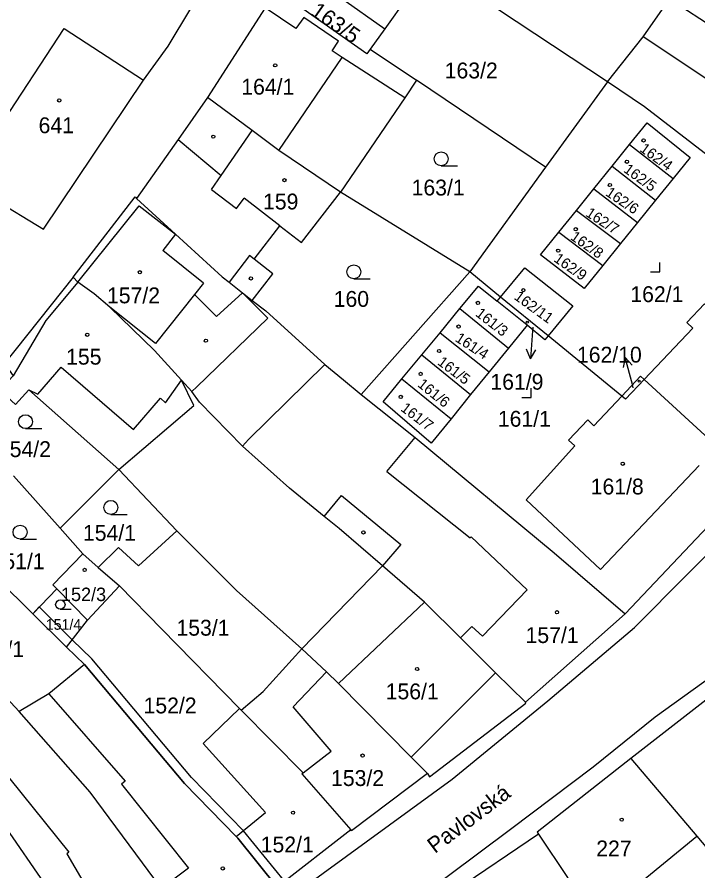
# Model space of a CAD drawing. Extents: x -600849 to -599899, y -1204328 to -1203436.
# Drawn here: x -600525.3 to -600452.2, y -1203727 to -1203635.4 of the extents above; entities that cross this region are included whole.
import ezdxf

# ---------------------------------------------------------------- set-up
doc = ezdxf.new("R2010")
doc.units = 0
for name, color, linetype in [('Vrstva 1', 7, 'Continuous'), ('Vrstva 13', 7, 'Continuous'), ('Vrstva 2', 7, 'Continuous'), ('Vrstva 3', 7, 'Continuous'), ('Vrstva 4', 7, 'Continuous'), ('Vrstva 5', 7, 'Continuous'), ('Vrstva 7', 7, 'Continuous')]:
    doc.layers.add(name, color=color, linetype=linetype)

msp = doc.modelspace()

# ---------------------------------------------------------------- linework, layer by layer
at = {"layer": 'Vrstva 1'}
for p, q in [((-600480.89, -1203629.76), (-600485.82, -1203636.68)), ((-600493.96, -1203630.88), (-600485.82, -1203636.68)), ((-600461.92, -1203642.39), (-600477.46, -1203632.09)), ((-600443.46, -1203641.26), (-600455.29, -1203633.46)), ((-600498.63, -1203634.44), (-600504.83, -1203644.05)), ((-600485.82, -1203636.68), (-600487.37, -1203638.87)), ((-600487.37, -1203638.87), (-600482.41, -1203642.21)), ((-600468.57, -1203651.53), (-600482.41, -1203642.21)), ((-600461.92, -1203642.39), (-600468.57, -1203651.53)), ((-600457.96, -1203645.05), (-600461.92, -1203642.39)), ((-600461.42, -1203651.42), (-600459.56, -1203649.11)), ((-600459.56, -1203649.11), (-600454.89, -1203652.74)), ((-600468.57, -1203651.53), (-600476.69, -1203662.78)), ((-600463.38, -1203653.85), (-600461.42, -1203651.42)), ((-600461.42, -1203651.42), (-600456.77, -1203655.07)), ((-600454.89, -1203652.74), (-600456.77, -1203655.07)), ((-600476.69, -1203662.78), (-600490.56, -1203654.23)), ((-600465.25, -1203656.17), (-600463.38, -1203653.85)), ((-600463.38, -1203653.85), (-600458.71, -1203657.46)), ((-600456.77, -1203655.07), (-600458.71, -1203657.46)), ((-600467.13, -1203658.49), (-600465.25, -1203656.17)), ((-600465.25, -1203656.17), (-600460.53, -1203659.71)), ((-600458.71, -1203657.46), (-600460.53, -1203659.71)), ((-600467.13, -1203658.49), (-600462.44, -1203662.08)), ((-600460.53, -1203659.71), (-600462.44, -1203662.08)), ((-600519.23, -1203663.35), (-600526.62, -1203672.61)), ((-600488.35, -1203675.92), (-600476.69, -1203662.78)), ((-600473.4, -1203665.48), (-600476.69, -1203662.78)), ((-600473.77, -1203665.92), (-600473.4, -1203665.48)), ((-600468.3, -1203669.64), (-600473.4, -1203665.48)), ((-600470.56, -1203668.5), (-600473.77, -1203665.92)), ((-600479.88, -1203669.3), (-600477.76, -1203666.71)), ((-600477.76, -1203666.71), (-600472.55, -1203670.96)), ((-600470.56, -1203668.5), (-600472.55, -1203670.96)), ((-600481.84, -1203671.68), (-600479.88, -1203669.3)), ((-600479.88, -1203669.3), (-600474.62, -1203673.49)), ((-600460.4, -1203676.09), (-600468.3, -1203669.64)), ((-600472.55, -1203670.96), (-600474.62, -1203673.49)), ((-600483.97, -1203674.26), (-600481.84, -1203671.68)), ((-600481.84, -1203671.68), (-600476.61, -1203675.93)), ((-600474.62, -1203673.49), (-600476.61, -1203675.93)), ((-600483.97, -1203674.26), (-600478.71, -1203678.52)), ((-600450.16, -1203681.49), (-600457.99, -1203674.31)), ((-600476.61, -1203675.93), (-600478.71, -1203678.52)), ((-600520.64, -1203690.25), (-600525.62, -1203684.64)), ((-600514.34, -1203683.98), (-600520.64, -1203690.25)), ((-600508.13, -1203690.57), (-600514.34, -1203683.98)), ((-600520.64, -1203690.25), (-600518.19, -1203693.01)), ((-600518.19, -1203693.01), (-600516.56, -1203694.48)), ((-600516.56, -1203694.48), (-600514.28, -1203696.45)), ((-600528.21, -1203694.86), (-600523.58, -1203699.44)), ((-600514.28, -1203696.45), (-600517.7, -1203700.15)), ((-600523.58, -1203699.44), (-600520.99, -1203696.78)), ((-600517.7, -1203700.15), (-600520.99, -1203696.78)), ((-600519.95, -1203703.04), (-600523.58, -1203699.44)), ((-600519.95, -1203703.04), (-600517.7, -1203700.15)), ((-600460.04, -1203699.45), (-600470.74, -1203708.95)), ((-600518.02, -1203704.91), (-600519.95, -1203703.04)), ((-600518.02, -1203704.91), (-600521.86, -1203708.03)), ((-600448.26, -1203706.28), (-600459.42, -1203714.97)), ((-600525.04, -1203709.94), (-600527.47, -1203707.35)), ((-600521.86, -1203708.03), (-600525.04, -1203709.94)), ((-600505.3, -1203713.38), (-600501.38, -1203709.63)), ((-600501.38, -1203709.63), (-600501.21, -1203709.81)), ((-600489.46, -1203722.64), (-600497.34, -1203728.8)), ((-600469.34, -1203723.1), (-600480.16, -1203730.41))]:
    msp.add_line(p, q, dxfattribs=at)
for points in [[(-600468.32, -1203708.8), (-600459.02, -1203700.91), (-600447.7, -1203689.53), (-600398.8, -1203640.57), (-600381.76, -1203623.36), (-600376.64, -1203618.38), (-600366.85, -1203610.56), (-600358.79, -1203604.64), (-600335.27, -1203586.75), (-600326.92, -1203580.15), (-600315.47, -1203571.41), (-600313.87, -1203569.96), (-600309.19, -1203565.44), (-600307.64, -1203563.87), (-600297.75, -1203553.71), (-600294.09, -1203550.64), (-600277.89, -1203537.3), (-600263.22, -1203524.94), (-600248.8, -1203512.9), (-600231.21, -1203497.85)], [(-600516.74, -1203754.05), (-600500.93, -1203742.85), (-600482.23, -1203729.97), (-600472.33, -1203722.55), (-600463.46, -1203715.87), (-600456.83, -1203710.5), (-600450.71, -1203706.1), (-600424.21, -1203680.79), (-600406.92, -1203664.19), (-600381.77, -1203639.93), (-600378.09, -1203636.25), (-600365.25, -1203624.15), (-600362.86, -1203622.3), (-600356.33, -1203617.3), (-600346.34, -1203609.78), (-600334.21, -1203600.46), (-600309.35, -1203581.63), (-600259.57, -1203537.67), (-600253.46, -1203531.77)], [(-600487.37, -1203638.87), (-600487.73, -1203639.37), (-600495.91, -1203633.62), (-600495.64, -1203633.24)], [(-600461.92, -1203642.39), (-600458.12, -1203637.56), (-600455.29, -1203633.46)], [(-600527.86, -1203654.9), (-600522.41, -1203658.19), (-600511.68, -1203642.2), (-600509.04, -1203638.54), (-600506.63, -1203634.51)], [(-600482.41, -1203642.21), (-600483.66, -1203644.11), (-600490.56, -1203654.23)], [(-600504.83, -1203644.05), (-600507.99, -1203648.55), (-600512.45, -1203654.88)], [(-600490.56, -1203654.23), (-600497.17, -1203649.74), (-600500.04, -1203647.61), (-600504.83, -1203644.05)], [(-600430.59, -1203668.48), (-600435.56, -1203663.69), (-600446.11, -1203655.07), (-600451.09, -1203650.36), (-600457.96, -1203645.05)], [(-600459.56, -1203649.11), (-600457.67, -1203646.77), (-600453.07, -1203650.49), (-600454.89, -1203652.74)], [(-600500.03, -1203665.83), (-600497.83, -1203662.99), (-600499.84, -1203661.41), (-600497.07, -1203657.82), (-600494.76, -1203659.61), (-600490.56, -1203654.23)], [(-600519.23, -1203663.35), (-600512.6, -1203654.73), (-600512.45, -1203654.88)], [(-600512.45, -1203654.88), (-600508.26, -1203658.71), (-600503.26, -1203663.3), (-600502.52, -1203663.88), (-600501.09, -1203665), (-600500.03, -1203665.83)], [(-600462.44, -1203662.08), (-600464.44, -1203664.56), (-600469.1, -1203660.94), (-600467.13, -1203658.49)], [(-600457.99, -1203674.31), (-600452.79, -1203668.81), (-600453.42, -1203668.19), (-600451.54, -1203666.19), (-600450.87, -1203666.76), (-600445.65, -1203661.21), (-600437.84, -1203668.56), (-600440.62, -1203671.46), (-600439.79, -1203672.28), (-600446.52, -1203679.36), (-600447.21, -1203678.64), (-600450.16, -1203681.49)], [(-600473.4, -1203665.48), (-600470.79, -1203662.32), (-600465.65, -1203666.41), (-600468.3, -1203669.64)], [(-600507.63, -1203674.37), (-600510.52, -1203671.2), (-600515.31, -1203666.56), (-600517, -1203665.14), (-600518.72, -1203663.86), (-600519.23, -1203663.35)], [(-600477.76, -1203666.71), (-600475.77, -1203664.31), (-600473.77, -1203665.92)], [(-600500.03, -1203665.83), (-600498.57, -1203666.95), (-600492.25, -1203672.71)], [(-600468.3, -1203669.64), (-600468.64, -1203670.05), (-600470.56, -1203668.5)], [(-600526.62, -1203672.61), (-600525.67, -1203673.91), (-600527.13, -1203675.45), (-600525.43, -1203677), (-600523.99, -1203675.43), (-600514.34, -1203683.98)], [(-600492.25, -1203672.71), (-600500.42, -1203680.77), (-600501.09, -1203681.48)], [(-600492.25, -1203672.71), (-600490.26, -1203674.36), (-600488.35, -1203675.92)], [(-600514.34, -1203683.98), (-600506.29, -1203677.1), (-600507.63, -1203674.37)], [(-600501.09, -1203681.48), (-600505.7, -1203676.76), (-600506.51, -1203675.6), (-600507.63, -1203674.37)], [(-600478.71, -1203678.52), (-600480.84, -1203681.14), (-600485.98, -1203676.7), (-600483.97, -1203674.26)], [(-600460.4, -1203676.09), (-600458.39, -1203673.95), (-600457.99, -1203674.31)], [(-600457.99, -1203674.31), (-600459.99, -1203676.43), (-600460.4, -1203676.09)], [(-600488.35, -1203675.92), (-600482.56, -1203680.54), (-600467.64, -1203692.93), (-600460.04, -1203699.45)], [(-600452.11, -1203683.55), (-600462.69, -1203694.7), (-600470.65, -1203687.23), (-600465.44, -1203681.45), (-600466.1, -1203680.84), (-600464.04, -1203678.65), (-600463.39, -1203679.27), (-600460.4, -1203676.09)], [(-600470.74, -1203708.95), (-600473.94, -1203705.78), (-600477.71, -1203702.03), (-600481.56, -1203698.21), (-600486.07, -1203694.32), (-600490.72, -1203690.31), (-600492.32, -1203689.01), (-600496.04, -1203685.99), (-600501.09, -1203681.48)], [(-600460.04, -1203699.45), (-600448.61, -1203687.36), (-600448.84, -1203687.11)], [(-600516.56, -1203694.48), (-600514.36, -1203692.35), (-600512.23, -1203694.31), (-600508.13, -1203690.57)], [(-600508.13, -1203690.57), (-600501.72, -1203696.94), (-600494.71, -1203703.2)], [(-600520.99, -1203696.78), (-600521.41, -1203696.35), (-600518.19, -1203693.01)], [(-600514.28, -1203696.45), (-600509.73, -1203701.1), (-600501.38, -1203709.63)], [(-600501.21, -1203709.81), (-600498.86, -1203707.78), (-600494.71, -1203703.2)], [(-600494.71, -1203703.2), (-600492.05, -1203705.68), (-600490.79, -1203706.92), (-600482.98, -1203714.84), (-600481.24, -1203716.6)], [(-600501.74, -1203723.36), (-600507.31, -1203717.65), (-600518.02, -1203704.91)], [(-600514.56, -1203740.22), (-600518.55, -1203733.82), (-600530.21, -1203716.96), (-600533.65, -1203713.17), (-600537.95, -1203708.73)], [(-600503.75, -1203735.54), (-600478.6, -1203717.19), (-600468.32, -1203708.8)], [(-600481.24, -1203716.6), (-600481.03, -1203716.94), (-600470.68, -1203709.05), (-600470.74, -1203708.95)], [(-600505.91, -1203735.13), (-600509.78, -1203728.93), (-600517.42, -1203718.58), (-600525.04, -1203709.94)], [(-600501.21, -1203709.81), (-600494.58, -1203716.51), (-600494.72, -1203716.63), (-600489.46, -1203722.64)], [(-600501.74, -1203723.36), (-600498.61, -1203720.79), (-600505.3, -1203713.38)], [(-600459.42, -1203714.97), (-600469.47, -1203722.88), (-600469.34, -1203723.1)], [(-600459.42, -1203714.97), (-600452.35, -1203723.33), (-600449.14, -1203727.13), (-600448.79, -1203726.83), (-600431.48, -1203744.63), (-600426.82, -1203748.42), (-600419.28, -1203756.23), (-600409.09, -1203765.55), (-600409.58, -1203766.13)], [(-600481.24, -1203716.6), (-600489.4, -1203722.74), (-600489.46, -1203722.64)], [(-600469.34, -1203723.1), (-600466.22, -1203727.76), (-600462.39, -1203731.53), (-600461.96, -1203731.92), (-600457.59, -1203735.9), (-600452.74, -1203740.82), (-600433.78, -1203757.11)], [(-600497.34, -1203728.8), (-600501.57, -1203723.53), (-600501.74, -1203723.36)]]:
    msp.add_lwpolyline(points, dxfattribs=at)
at = {"layer": 'Vrstva 13'}
msp.add_lwpolyline([(-600523.58, -1203699.44), (-600519.95, -1203703.04), (-600518.02, -1203704.91), (-600507.31, -1203717.65), (-600501.74, -1203723.36), (-600501.57, -1203723.53), (-600497.34, -1203728.8), (-600496.55, -1203728.18), (-600500.97, -1203722.73), (-600506.54, -1203717.01), (-600517.25, -1203704.27), (-600519.34, -1203702.25), (-600522.88, -1203698.72)], close=True, dxfattribs=at)
at = {"layer": 'Vrstva 3'}
for p, q in [((-600479.773, -1203651.39), (-600478.023, -1203651.39)), ((-600456.3, -1203662.77), (-600456.3, -1203661.77)), ((-600457.301, -1203662.77), (-600456.3, -1203662.77)), ((-600489.133, -1203663.51), (-600487.383, -1203663.51)), ((-600470.11, -1203676.23), (-600470.11, -1203675.23)), ((-600471.111, -1203676.23), (-600470.11, -1203676.23)), ((-600524.353, -1203679.59), (-600522.603, -1203679.59)), ((-600515.193, -1203688.79), (-600513.443, -1203688.79)), ((-600524.933, -1203691.44), (-600523.183, -1203691.44)), ((-600520.615, -1203698.97), (-600519.443, -1203698.97))]:
    msp.add_line(p, q, dxfattribs=at)
for centre, radius in [((-600479.773, -1203650.64), 0.75), ((-600489.133, -1203662.76), 0.75), ((-600524.353, -1203678.84), 0.75), ((-600515.193, -1203688.04), 0.75), ((-600524.933, -1203690.69), 0.75), ((-600520.615, -1203698.467), 0.502)]:
    msp.add_circle(centre, radius, dxfattribs=at)
at = {"layer": 'Vrstva 4'}
for p, q in [((-600495.36, -1203636.64), (-600498.63, -1203634.44)), ((-600494.5, -1203635.49), (-600495.36, -1203636.64)), ((-600490.78, -1203638), (-600494.5, -1203635.49)), ((-600530.42, -1203652.15), (-600520.19, -1203636.64)), ((-600520.19, -1203636.64), (-600511.68, -1203642.2)), ((-600491.46, -1203639.04), (-600490.78, -1203638)), ((-600446.2, -1203645.49), (-600458.12, -1203637.56)), ((-600497.17, -1203649.74), (-600490.37, -1203639.75)), ((-600490.37, -1203639.75), (-600491.46, -1203639.04)), ((-600483.66, -1203644.11), (-600490.37, -1203639.75)), ((-600503.36, -1203652.41), (-600500.04, -1203647.61)), ((-600507.99, -1203648.55), (-600503.36, -1203652.41)), ((-600504.4, -1203653.92), (-600503.36, -1203652.41)), ((-600504.4, -1203653.92), (-600501.73, -1203655.97)), ((-600501.73, -1203655.97), (-600500.88, -1203654.86)), ((-600497.07, -1203657.82), (-600500.88, -1203654.86)), ((-600518.72, -1203663.86), (-600512.15, -1203655.68)), ((-600512.15, -1203655.68), (-600508.26, -1203658.71)), ((-600508.26, -1203658.71), (-600509.63, -1203660.48)), ((-600505.25, -1203663.98), (-600509.63, -1203660.48)), ((-600500.34, -1203661.01), (-600502.52, -1203663.88)), ((-600499.84, -1203661.41), (-600500.34, -1203661.01)), ((-600518.72, -1203663.86), (-600522.17, -1203667.99)), ((-600505.25, -1203663.98), (-600506.21, -1203665.18)), ((-600506.21, -1203665.18), (-600510.42, -1203670.44)), ((-600503.86, -1203667.57), (-600506.21, -1203665.18)), ((-600501.09, -1203665), (-600503.86, -1203667.57)), ((-600501.09, -1203665), (-600498.35, -1203667.73)), ((-600510.42, -1203670.44), (-600515.31, -1203666.56)), ((-600522.17, -1203667.99), (-600525.67, -1203673.91)), ((-600498.35, -1203667.73), (-600505.99, -1203675.1)), ((-600523.01, -1203675.9), (-600520.51, -1203672.99)), ((-600520.51, -1203672.99), (-600512.75, -1203679.67)), ((-600509.32, -1203676.81), (-600507.63, -1203674.37)), ((-600523.99, -1203675.43), (-600523.01, -1203675.9)), ((-600505.99, -1203675.1), (-600506.51, -1203675.6)), ((-600512.75, -1203679.67), (-600509.88, -1203676.33)), ((-600509.88, -1203676.33), (-600509.32, -1203676.81)), ((-600485.6, -1203684.17), (-600482.56, -1203680.54)), ((-600485.6, -1203684.17), (-600476.64, -1203691.32)), ((-600492.32, -1203689.01), (-600490.44, -1203686.75)), ((-600490.44, -1203686.75), (-600484.11, -1203692.03)), ((-600484.11, -1203692.03), (-600486.07, -1203694.32)), ((-600476.64, -1203691.32), (-600476.54, -1203691.21)), ((-600476.54, -1203691.21), (-600470.55, -1203696.9)), ((-600486.07, -1203694.32), (-600494.71, -1203703.2)), ((-600470.55, -1203696.9), (-600475.33, -1203701.85)), ((-600481.56, -1203698.21), (-600490.79, -1203706.92)), ((-600476.49, -1203700.83), (-600477.71, -1203702.03)), ((-600475.33, -1203701.85), (-600476.49, -1203700.83)), ((-600535.49, -1203705.4), (-600519.71, -1203725.04)), ((-600495.65, -1203709.45), (-600492.05, -1203705.68)), ((-600473.94, -1203705.78), (-600482.98, -1203714.84)), ((-600521.86, -1203708.03), (-600513.65, -1203717.42)), ((-600491.55, -1203714.21), (-600495.65, -1203709.45)), ((-600494.58, -1203716.51), (-600491.55, -1203714.21)), ((-600513.65, -1203717.42), (-600514.06, -1203717.75)), ((-600514.06, -1203717.75), (-600506.88, -1203726.75)), ((-600462.39, -1203731.53), (-600452.35, -1203723.33)), ((-600519.71, -1203725.04), (-600519.9, -1203725.2)), ((-600519.9, -1203725.2), (-600515.63, -1203732.52)), ((-600506.88, -1203726.75), (-600509.78, -1203728.93))]:
    msp.add_line(p, q, dxfattribs=at)
at = {"layer": 'Vrstva 5'}
for centre, radius in [((-600497.567, -1203640.609), 0.175), ((-600520.737, -1203644.369), 0.175), ((-600504.207, -1203648.259), 0.175), ((-600458.057, -1203648.659), 0.175), ((-600459.847, -1203650.959), 0.175), ((-600496.577, -1203652.929), 0.175), ((-600461.667, -1203653.449), 0.175), ((-600465.337, -1203658.199), 0.175), ((-600467.207, -1203660.489), 0.175), ((-600512.087, -1203662.809), 0.175), ((-600500.177, -1203663.469), 0.175), ((-600470.957, -1203664.729), 0.175), ((-600475.827, -1203666.099), 0.175), ((-600470.535, -1203668.159), 0.117), ((-600477.907, -1203668.639), 0.175), ((-600517.727, -1203669.519), 0.175), ((-600504.997, -1203670.149), 0.175), ((-600479.987, -1203671.259), 0.175), ((-600481.967, -1203673.719), 0.175), ((-600458.535, -1203674.499), 0.117), ((-600484.097, -1203676.179), 0.175), ((-600460.297, -1203683.359), 0.175), ((-600488.107, -1203690.729), 0.175), ((-600518.007, -1203694.749), 0.175), ((-600467.347, -1203699.289), 0.175), ((-600482.347, -1203705.379), 0.175), ((-600488.197, -1203714.669), 0.175), ((-600495.657, -1203720.789), 0.175), ((-600460.407, -1203721.539), 0.175), ((-600503.187, -1203726.779), 0.175)]:
    msp.add_circle(centre, radius, dxfattribs=at)
at = {"layer": 'Vrstva 7'}
for p, q in [((-600469.97, -1203669.1), (-600470.179, -1203672.094)), ((-600469.94, -1203668.7), (-600469.97, -1203669.1)), ((-600470.179, -1203672.094), (-600470.609, -1203671.06)), ((-600470.179, -1203672.094), (-600469.61, -1203671.13)), ((-600460.037, -1203671.941), (-600460.261, -1203673.038)), ((-600459.26, -1203674.84), (-600460.037, -1203671.941)), ((-600460.037, -1203671.941), (-600459.294, -1203672.779)), ((-600459.16, -1203675.22), (-600459.26, -1203674.84))]:
    msp.add_line(p, q, dxfattribs=at)

# ---------------------------------------------------------------- texts
at = {"layer": 'Vrstva 2'}
for s, height, rotation, p in [('163/5', 1.7, 325, (-600493.899, -1203635.104)), ('162/4', 1.14, 324, (-600458.554, -1203649.76)), ('162/5', 1.14, 324, (-600460.294, -1203651.98)), ('162/6', 1.14, 326, (-600462.232, -1203654.505)), ('162/7', 1.14, 327, (-600464.365, -1203656.713)), ('162/8', 1.14, 325, (-600465.998, -1203659.218)), ('162/9', 1.14, 325, (-600467.778, -1203661.578)), ('162/11', 1.14, 324, (-600472.036, -1203665.625)), ('161/3', 1.14, 322, (-600476.173, -1203667.417)), ('161/4', 1.14, 327, (-600478.355, -1203670.143)), ('161/5', 1.14, 323, (-600480.249, -1203672.634)), ('161/6', 1.14, 321, (-600482.387, -1203674.99)), ('161/7', 1.14, 323, (-600484.199, -1203677.594))]:
    msp.add_text(s, height=height, rotation=rotation, dxfattribs=at).set_placement(p)
for s, height, p in [('163/2', 1.7, (-600479.388, -1203642.01)), ('164/1', 1.7, (-600501.208, -1203643.75)), ('641', 1.7, (-600522.945, -1203647.89)), ('163/1', 1.7, (-600482.938, -1203654.57)), ('159', 1.7, (-600498.875, -1203656.07)), ('157/2', 1.7, (-600515.608, -1203666.14)), ('162/1', 1.7, (-600459.478, -1203666.01)), ('160', 1.7, (-600491.295, -1203666.52)), ('155', 1.7, (-600519.995, -1203672.72)), ('162/10', 1.7, (-600465.205, -1203672.5)), ('161/9', 1.7, (-600474.487, -1203675.408)), ('161/1', 1.7, (-600473.688, -1203679.38)), ('154/2', 1.7, (-600527.308, -1203682.64)), ('161/8', 1.7, (-600463.728, -1203686.65)), ('154/1', 1.7, (-600518.188, -1203691.62)), ('151/1', 1.7, (-600527.988, -1203694.67)), ('152/3', 1.443, (-600520.539, -1203698.091)), ('151/4', 1.139, (-600522.18, -1203701.169)), ('153/1', 1.7, (-600508.158, -1203701.8)), ('157/1', 1.7, (-600470.718, -1203702.59)), ('149/1', 1.7, (-600530.188, -1203704.1)), ('156/1', 1.7, (-600485.718, -1203708.63)), ('152/2', 1.7, (-600511.69, -1203710.14)), ('153/2', 1.7, (-600491.578, -1203717.93)), ('152/1', 1.7, (-600499.12, -1203725.06)), ('227', 1.7, (-600463.135, -1203725.48))]:
    msp.add_text(s, height=height, dxfattribs=at).set_placement(p)
at = {"layer": 'Vrstva 7'}
msp.add_text('Pavlovská', height=1.7, rotation=37, dxfattribs=at).set_placement((-600480.439, -1203725.231))

doc.saveas('drawing.dxf')
